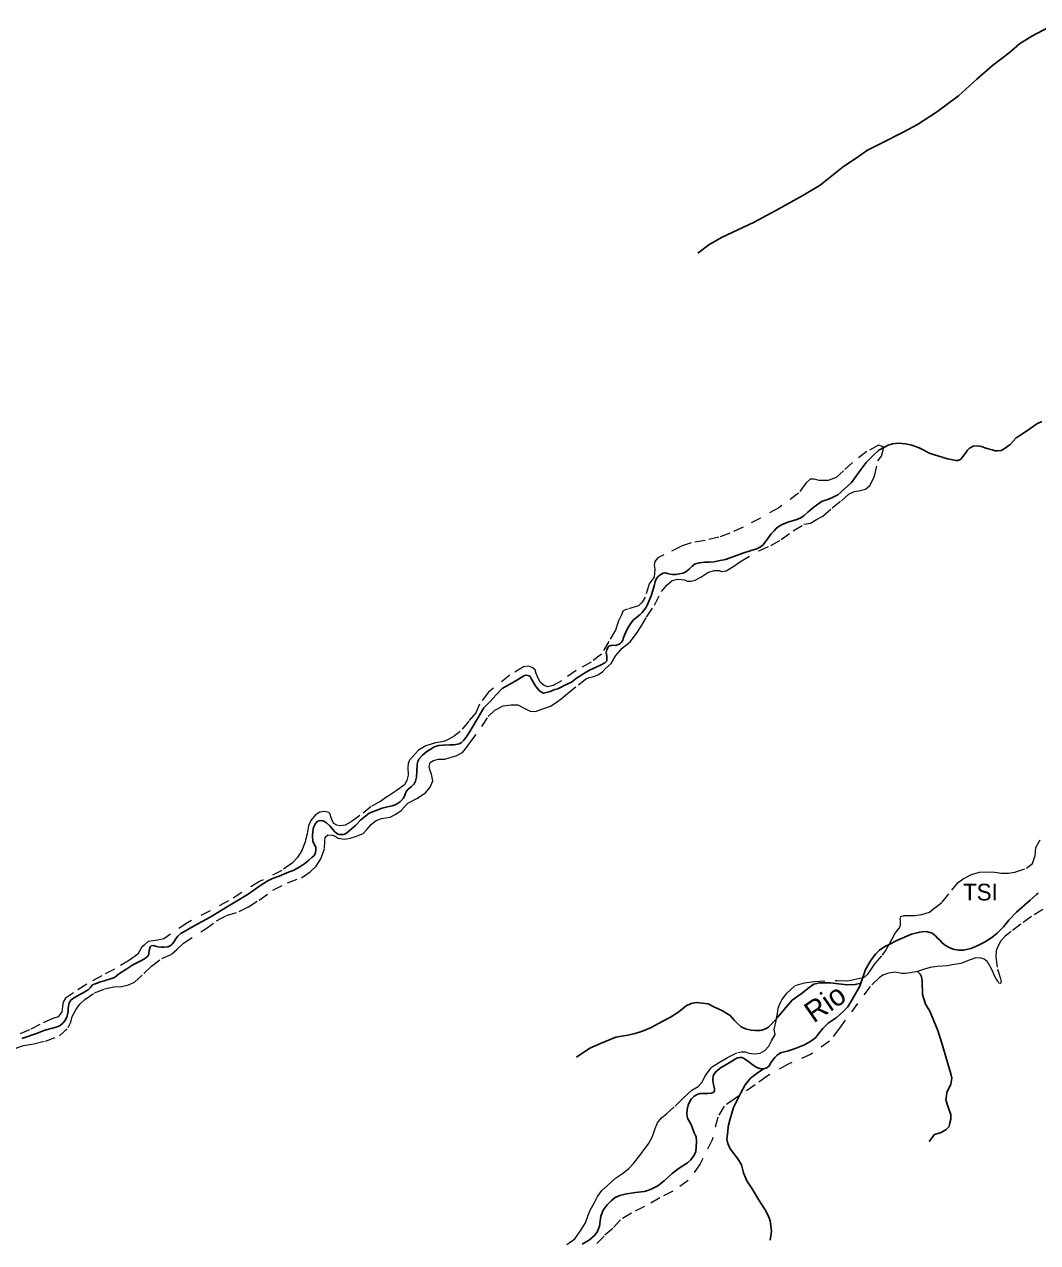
# Model space of a CAD drawing. Extents: x 391.8 to 446, y 8452 to 8507.5.
# Drawn here: x 426.58 to 436.28, y 8458.87 to 8470.53 of the extents above; entities that cross this region are included whole.
import ezdxf
from ezdxf.enums import TextEntityAlignment as Align

# ---------------------------------------------------------------- set-up
doc = ezdxf.new("R2010")
doc.units = 0
doc.header["$LTSCALE"] = 0.064
doc.linetypes.add('LONG_DASHED', pattern=[7.5, 6, -1.5])
doc.linetypes.add('SHORT_DASHED', pattern=[2.7, 1.5, -1.2])
for name, color, linetype, lineweight in [('21', 7, 'SHORT_DASHED', 13), ('7', 7, 'Continuous', 25), ('9', 7, 'LONG_DASHED', 25)]:
    doc.layers.add(name, color=color, linetype=linetype, lineweight=lineweight)
doc.layers.add('61', color=7, linetype='Continuous')

msp = doc.modelspace()

# ---------------------------------------------------------------- linework, layer by layer
at = {"layer": '21'}
for points in [[(434.7921, 8466.4881), (434.7588, 8466.5004), (434.6476, 8466.4391), (434.5089, 8466.3352), (434.4223, 8466.2544), (434.3529, 8466.1909), (434.2778, 8466.1621), (434.1911, 8466.1621), (434.1449, 8466.1736), (434.1045, 8466.1736), (434.063, 8466.138), (433.9937, 8466.0399), (433.803, 8465.9014), (433.6297, 8465.8033), (433.4621, 8465.7168), (433.335, 8465.6591), (433.231, 8465.6187), (433.0981, 8465.5898), (432.9652, 8465.5667), (432.867, 8465.5321), (432.7052, 8465.4513), (432.6474, 8465.4225), (432.6185, 8465.3878), (432.6127, 8465.3532), (432.6185, 8465.3128), (432.6127, 8465.2378), (432.565, 8465.1724), (432.5246, 8465.0454), (432.4957, 8464.9992), (432.461, 8464.9646), (432.357, 8464.93), (432.3339, 8464.9242), (432.3108, 8464.9127), (432.2992, 8464.8781), (432.269, 8464.8182), (432.2401, 8464.7316), (432.1765, 8464.622), (432.1072, 8464.5008), (432.0089, 8464.4258), (431.8645, 8464.345), (431.7258, 8464.2469), (431.6449, 8464.2008), (431.5929, 8464.1892), (431.5583, 8464.2008), (431.5236, 8464.2296), (431.5005, 8464.27), (431.4831, 8464.3162), (431.4716, 8464.3508), (431.4427, 8464.3739), (431.408, 8464.3854), (431.3618, 8464.3796), (431.2289, 8464.2989), (431.0267, 8464.1373), (430.94, 8464.0219), (430.9053, 8463.9411), (430.836, 8463.8603), (430.7551, 8463.7622), (430.6973, 8463.716), (430.6453, 8463.6872), (430.5991, 8463.6641), (430.5182, 8463.6526), (430.4258, 8463.6237), (430.3564, 8463.5833), (430.2987, 8463.5198), (430.2698, 8463.4852), (430.2582, 8463.4564), (430.2524, 8463.416), (430.256, 8463.3427), (430.2445, 8463.2908), (430.2214, 8463.2504), (430.1405, 8463.1927), (430.0538, 8463.135), (429.996, 8463.0946), (429.9036, 8463.0426), (429.7938, 8462.9561), (429.7129, 8462.8984), (429.6551, 8462.8638), (429.6031, 8462.858), (429.5742, 8462.8638), (429.5454, 8462.8811), (429.5338, 8462.9042), (429.5165, 8462.9445), (429.5107, 8462.9734), (429.4991, 8462.9849), (429.4587, 8462.9965), (429.4125, 8462.9907), (429.3662, 8462.9619), (429.3258, 8462.9099), (429.3027, 8462.858), (429.2911, 8462.783), (429.268, 8462.6964)], [(432.9284, 8465.2003), (432.966, 8465.2003), (433.0037, 8465.2079), (433.0565, 8465.238), (433.1243, 8465.2831), (433.1846, 8465.3019), (433.2336, 8465.3019), (433.2524, 8465.2907), (433.3014, 8465.2982), (433.3654, 8465.3358), (433.437, 8465.3885), (433.6141, 8465.4901), (433.7272, 8465.539), (433.8264, 8465.5968), (433.9432, 8465.6796), (434.045, 8465.7435), (434.109, 8465.7548), (434.1655, 8465.7887), (434.2258, 8465.8226), (434.3163, 8465.9016), (434.4029, 8465.9693), (434.4783, 8466.0333), (434.5273, 8466.0559), (434.5687, 8466.0634), (434.6328, 8466.0785), (434.678, 8466.1161), (434.7194, 8466.2026), (434.7534, 8466.3494), (434.7883, 8466.3957), (434.8079, 8466.4781), (434.7921, 8466.4881)], [(432.6826, 8465.1008), (432.7316, 8465.161), (432.7844, 8465.2062), (432.8333, 8465.2175), (432.8718, 8465.2154), (432.902, 8465.2116), (432.9284, 8465.2003)], [(426.9205, 8460.8489), (427.0034, 8460.928), (427.0298, 8460.9806), (427.0411, 8461.0333), (427.0767, 8461.0995), (427.1143, 8461.1522), (427.1633, 8461.1974), (427.2538, 8461.2613), (427.3517, 8461.299), (427.4384, 8461.3178), (427.5137, 8461.3215), (427.5816, 8461.3366), (427.6381, 8461.3629), (427.7285, 8461.4457), (427.8001, 8461.5172), (427.8981, 8461.5887), (427.9923, 8461.6301), (428.0413, 8461.6753), (428.1053, 8461.7355), (428.3126, 8461.871), (428.4234, 8461.9482), (428.5176, 8462.0009), (428.6382, 8462.0385), (428.7286, 8462.0837), (428.8303, 8462.1477), (428.9622, 8462.2418), (429.1016, 8462.3133), (429.2373, 8462.3622), (429.3202, 8462.4186), (429.3767, 8462.4713), (429.4219, 8462.5428), (429.4558, 8462.6407), (429.4601, 8462.7133), (429.4639, 8462.7509), (429.4865, 8462.7735), (429.5317, 8462.7697), (429.5581, 8462.7584), (429.5882, 8462.7396), (429.6448, 8462.7321), (429.7013, 8462.7396), (429.7616, 8462.7584), (429.8256, 8462.7848), (429.8633, 8462.8262), (429.9048, 8462.8751), (429.95, 8462.909), (430.0027, 8462.9278), (430.0856, 8462.9428), (430.1384, 8462.9692), (430.1911, 8463.0068), (430.2552, 8463.0745), (430.3396, 8463.1209), (430.4225, 8463.1736), (430.4677, 8463.23), (430.4941, 8463.2902), (430.479, 8463.3542), (430.4677, 8463.3843), (430.4564, 8463.4257), (430.4677, 8463.4633), (430.4979, 8463.4821), (430.5468, 8463.4972), (430.6071, 8463.4972), (430.6599, 8463.5122), (430.7239, 8463.5311), (430.7767, 8463.5612), (430.8068, 8463.595), (430.8483, 8463.6515), (430.9624, 8463.808), (431.0227, 8463.9058), (431.0868, 8463.966), (431.1659, 8464.0074), (431.2412, 8464.0149), (431.3053, 8464.0149), (431.3731, 8463.9811), (431.4259, 8463.9547), (431.4749, 8463.951), (431.5352, 8463.9736), (431.6181, 8464.0037), (431.7047, 8464.0601), (431.7838, 8464.1278), (431.8856, 8464.2069), (431.9554, 8464.2616), (431.9893, 8464.2767), (432.0345, 8464.288), (432.0722, 8464.303), (432.1174, 8464.3331), (432.1438, 8464.3595), (432.2003, 8464.4122), (432.2455, 8464.4874), (432.3058, 8464.5589), (432.3812, 8464.6191), (432.4415, 8464.6982), (432.4829, 8464.7621), (432.5394, 8464.8562), (432.6148, 8464.9691), (432.6826, 8465.1008)], [(435.1744, 8462.0111), (435.245, 8462.0334), (435.2859, 8462.0631), (435.3677, 8462.1299), (435.4614, 8462.2432), (435.5209, 8462.3174), (435.5692, 8462.3509), (435.6473, 8462.3917), (435.7253, 8462.414), (435.8034, 8462.4177), (435.8703, 8462.414), (435.9335, 8462.4065), (436.0041, 8462.4065), (436.0636, 8462.414), (436.1751, 8462.4548), (436.2309, 8462.4993), (436.2569, 8462.5736), (436.2643, 8462.6516), (436.3052, 8462.7258)], [(429.268, 8462.6964), (429.2391, 8462.6214), (429.1929, 8462.5522), (429.1467, 8462.5002), (429.0484, 8462.431), (428.8347, 8462.3271), (428.5378, 8462.1396), (428.1449, 8461.9319), (427.9831, 8461.8222), (427.9195, 8461.7761), (427.8618, 8461.7645), (427.8155, 8461.7588), (427.7693, 8461.753), (427.7289, 8461.7184), (427.7058, 8461.6953), (427.6711, 8461.6318), (427.5902, 8461.5741), (427.4457, 8461.4876), (427.3244, 8461.4241), (427.18, 8461.3433), (427.0528, 8461.2625), (426.9777, 8461.2106), (426.9546, 8461.1702), (426.9488, 8461.1298), (426.9431, 8461.0778), (426.9084, 8461.0317), (426.8564, 8461.0144), (426.7323, 8460.9595), (426.6341, 8460.9076), (426.5128, 8460.8557)], [(436.3317, 8462.059), (436.2239, 8461.9922), (436.1198, 8461.918), (436.0269, 8461.8474), (435.9711, 8461.8029), (435.9302, 8461.7583), (435.8968, 8461.6989), (435.8856, 8461.6618), (435.8819, 8461.6061), (435.8968, 8461.4873), (435.9265, 8461.3982), (435.9339, 8461.3611), (435.9228, 8461.35), (435.9116, 8461.3537), (435.9005, 8461.3723), (435.8856, 8461.3945), (435.867, 8461.4242), (435.8485, 8461.4725), (435.8262, 8461.5133), (435.8001, 8461.5579), (435.7704, 8461.5839), (435.7407, 8461.5913), (435.6886, 8461.595), (435.6366, 8461.5764), (435.5456, 8461.5428), (435.4676, 8461.5279), (435.4192, 8461.5205), (435.3189, 8461.5131), (435.252, 8461.5019), (435.1999, 8461.4871), (435.1306, 8461.4666)], [(434.8596, 8461.7238), (434.8881, 8461.7773), (434.9142, 8461.8255), (434.9402, 8461.8589), (434.9588, 8461.8812), (434.9699, 8461.9072), (434.9699, 8461.948), (434.9662, 8461.9666), (434.9736, 8461.9926), (435.0034, 8462), (435.1075, 8462), (435.1744, 8462.0111)], [(434.6082, 8461.4088), (434.6279, 8461.4135), (434.6577, 8461.4394), (434.6837, 8461.4803), (434.7246, 8461.5397), (434.7952, 8461.6213), (434.825, 8461.6622), (434.8584, 8461.7216), (434.8596, 8461.7238)], [(435.1306, 8461.4666), (435.0661, 8461.4537), (435.0141, 8461.4463), (434.9769, 8461.4463), (434.9509, 8461.4537), (434.9137, 8461.4574), (434.8542, 8461.45), (434.7985, 8461.4314), (434.765, 8461.4054), (434.6772, 8461.3209), (434.3844, 8460.924)], [(433.7831, 8461.0161), (433.7903, 8461.0625), (433.7977, 8461.1145), (433.8126, 8461.1553), (433.8349, 8461.1962), (433.8795, 8461.2593), (433.9612, 8461.3298), (434.0505, 8461.3558), (434.1434, 8461.3707), (434.364, 8461.38), (434.4644, 8461.3763), (434.5499, 8461.3949), (434.6082, 8461.4088)], [(431.7765, 8458.8528), (431.8508, 8458.9084), (431.9066, 8458.9827), (431.9549, 8459.0606), (431.9809, 8459.1349), (431.9995, 8459.1832), (432.0404, 8459.2537), (432.0701, 8459.3131), (432.111, 8459.3688), (432.1631, 8459.417), (432.2411, 8459.4876), (432.308, 8459.5321), (432.3675, 8459.5804), (432.4121, 8459.6286), (432.4725, 8459.7056), (432.5059, 8459.7501), (432.558, 8459.8169), (432.5952, 8459.8875), (432.6212, 8459.9617), (432.6435, 8460.0174), (432.6807, 8460.0657), (432.729, 8460.1028), (432.8108, 8460.177), (432.8814, 8460.2476), (432.9334, 8460.2958), (432.9706, 8460.3292), (433.0338, 8460.3664), (433.071, 8460.4072), (433.1007, 8460.4666), (433.1602, 8460.5483), (433.2271, 8460.5928), (433.3126, 8460.6411), (433.4111, 8460.6913), (433.4483, 8460.695), (433.4817, 8460.695), (433.5189, 8460.6839), (433.5672, 8460.6764), (433.6267, 8460.6839), (433.6713, 8460.7099), (433.7085, 8460.7507), (433.7345, 8460.8027), (433.7679, 8460.8621), (433.7605, 8460.9103), (433.7828, 8461.0143), (433.7831, 8461.0161)], [(434.3844, 8460.924), (434.2903, 8460.7987), (434.1125, 8460.6734), (433.8929, 8460.5794), (433.6942, 8460.4645), (433.5791, 8460.3809), (433.4271, 8460.2777)], [(426.3591, 8460.6344), (426.4232, 8460.6833), (426.5023, 8460.7323), (426.5739, 8460.7586), (426.6756, 8460.7737), (426.7849, 8460.8), (426.9205, 8460.8489)], [(433.4271, 8460.2777), (433.3867, 8460.2503), (433.2821, 8460.1772), (433.2194, 8460.0727), (433.1671, 8459.8534), (433.0521, 8459.6236), (432.937, 8459.4669), (432.7906, 8459.3625), (432.6651, 8459.2998), (432.5187, 8459.2163), (432.3932, 8459.1536), (432.2886, 8459.0909), (432.2154, 8459.0074), (432.1317, 8458.9343), (432.0272, 8458.8298)]]:
    msp.add_lwpolyline(points, dxfattribs=at)
at = {"layer": '7'}
msp.add_line((434.5893, 8461.3534), (434.6082, 8461.4088), dxfattribs=at)
for points in [[(434.8079, 8466.4781), (434.8098, 8466.4792), (434.8511, 8466.4998), (434.8925, 8466.513), (434.9488, 8466.5186), (435.0164, 8466.513), (435.0765, 8466.4998), (435.1479, 8466.4755), (435.2531, 8466.4211), (435.4203, 8466.3704), (435.4686, 8466.3589), (435.5005, 8466.3532), (435.5174, 8466.3532), (435.5418, 8466.3626), (435.5606, 8466.3814), (435.5757, 8466.4039), (435.5926, 8466.4283), (435.6113, 8466.4527), (435.6301, 8466.4714), (435.6658, 8466.4902), (435.7053, 8466.4939), (435.7447, 8466.4864), (435.7748, 8466.4733), (435.8067, 8466.4639), (435.8461, 8466.4545), (435.8762, 8466.447), (435.8931, 8466.447), (435.9326, 8466.4508), (435.9626, 8466.4658), (436.0171, 8466.5071), (436.0753, 8466.569), (436.138, 8466.6091), (436.2056, 8466.656), (436.2751, 8466.7048), (436.3221, 8466.7254)], [(433.6282, 8465.5274), (433.6545, 8465.5462), (433.6714, 8465.5687), (433.6996, 8465.6081), (433.7315, 8465.6531), (433.7597, 8465.6812), (433.781, 8465.7063), (433.8073, 8465.7251), (433.8355, 8465.7401), (433.8918, 8465.7626), (433.9763, 8465.7889), (434.0139, 8465.8039), (434.0458, 8465.8264), (434.0815, 8465.8602), (434.1416, 8465.9089), (434.2205, 8465.9633), (434.2628, 8465.9773), (434.3191, 8465.9998), (434.368, 8466.0242), (434.4281, 8466.0749), (434.4994, 8466.1424), (434.584, 8466.2568), (434.6389, 8466.3348), (434.7065, 8466.4004), (434.761, 8466.4511), (434.8079, 8466.4781)], [(433.2281, 8465.3923), (433.2939, 8465.4055), (433.3746, 8465.4336), (433.461, 8465.4655), (433.5381, 8465.4936), (433.5925, 8465.5087), (433.6282, 8465.5274)], [(430.339, 8463.3774), (430.3428, 8463.4472), (430.3484, 8463.4754), (430.3634, 8463.4998), (430.3935, 8463.5335), (430.4348, 8463.5692), (430.4724, 8463.5917), (430.5062, 8463.6142), (430.5513, 8463.6255), (430.5907, 8463.6292), (430.6527, 8463.6348), (430.6959, 8463.6348), (430.7437, 8463.6421), (430.7644, 8463.6533), (430.7907, 8463.6796), (430.8207, 8463.719), (430.8677, 8463.7921), (430.9259, 8463.8934), (430.9804, 8463.9872), (431.0405, 8464.0491), (431.1006, 8464.1129), (431.157, 8464.1711), (431.2877, 8464.245), (431.3384, 8464.2787), (431.3628, 8464.2937), (431.3797, 8464.2994), (431.4023, 8464.2975), (431.4154, 8464.2937), (431.423, 8464.2881), (431.4361, 8464.2619), (431.4774, 8464.1924), (431.5131, 8464.1493), (431.5319, 8464.138), (431.5526, 8464.1287), (431.5657, 8464.1324), (431.6052, 8464.1399), (431.6371, 8464.153), (431.6596, 8464.1624), (431.6878, 8464.1681), (431.7216, 8464.1849), (431.7498, 8464.1999), (431.8193, 8464.2337), (431.8681, 8464.2712), (431.9282, 8464.3106), (431.9921, 8464.3463), (432.0616, 8464.3782), (432.1029, 8464.3988), (432.1405, 8464.4176), (432.148, 8464.4269), (432.1574, 8464.4382), (432.1593, 8464.4588), (432.1574, 8464.4832), (432.1518, 8464.517), (432.1574, 8464.5432), (432.1668, 8464.5658), (432.1781, 8464.577), (432.2081, 8464.5864), (432.2443, 8464.5837), (432.2613, 8464.5893), (432.2838, 8464.5987), (432.2951, 8464.6118), (432.3101, 8464.6325), (432.3176, 8464.6587), (432.3383, 8464.7056), (432.357, 8464.7469), (432.3833, 8464.79), (432.4096, 8464.8276), (432.4453, 8464.8538), (432.4735, 8464.8782), (432.4961, 8464.8989), (432.5317, 8464.9439), (432.5468, 8464.9758), (432.5811, 8465.0597), (432.6111, 8465.1516), (432.6224, 8465.1948), (432.6336, 8465.2248), (432.6449, 8465.2398), (432.6693, 8465.2585), (432.6975, 8465.2754), (432.7163, 8465.2792), (432.7388, 8465.2736), (432.752, 8465.2679), (432.7858, 8465.2642), (432.8177, 8465.2642), (432.8572, 8465.2698), (432.8891, 8465.2754), (432.9154, 8465.2886), (432.9473, 8465.3129), (432.9755, 8465.343), (433.0037, 8465.3636), (433.045, 8465.3749), (433.092, 8465.3805), (433.1408, 8465.3805), (433.1859, 8465.3842), (433.2281, 8465.3923)], [(430.2394, 8463.1898), (430.2563, 8463.2085), (430.2864, 8463.2311), (430.3127, 8463.2611), (430.3258, 8463.2873), (430.3352, 8463.3249), (430.339, 8463.3774)], [(427.0115, 8461.1639), (427.0284, 8461.1901), (427.0453, 8461.2033), (427.1081, 8461.2416), (427.1457, 8461.2603), (427.172, 8461.2754), (427.1927, 8461.2904), (427.2133, 8461.3072), (427.2283, 8461.3279), (427.2396, 8461.3391), (427.2659, 8461.3485), (427.3016, 8461.3616), (427.3467, 8461.3748), (427.4068, 8461.3935), (427.4462, 8461.4085), (427.4838, 8461.4386), (427.5646, 8461.4892), (427.6209, 8461.5286), (427.6904, 8461.5642), (427.7336, 8461.5849), (427.7505, 8461.598), (427.7656, 8461.613), (427.775, 8461.6299), (427.7794, 8461.6665), (427.7869, 8461.7003), (427.7981, 8461.7097), (427.8169, 8461.7134), (427.8395, 8461.7078), (427.8639, 8461.7003), (427.8921, 8461.6984), (427.9221, 8461.6965), (427.9578, 8461.7003), (427.9785, 8461.7097), (427.9954, 8461.7247), (428.0142, 8461.7472), (428.0311, 8461.7753), (428.0536, 8461.8016), (428.0799, 8461.8279), (428.2095, 8461.901), (428.3617, 8461.9854), (428.5505, 8462.0991), (428.7252, 8462.206), (428.8379, 8462.2848), (428.9082, 8462.3289), (428.9571, 8462.3551), (429.0228, 8462.3777), (429.0961, 8462.4077), (429.1618, 8462.4339), (429.22, 8462.4658), (429.267, 8462.4977), (429.3064, 8462.5315), (429.3384, 8462.5577), (429.359, 8462.5784), (429.3703, 8462.6046), (429.3741, 8462.6253), (429.3741, 8462.6515), (429.3665, 8462.6684), (429.3459, 8462.7078), (429.3402, 8462.7585), (429.344, 8462.8091), (429.3517, 8462.8435), (429.3668, 8462.8754), (429.3818, 8462.8961), (429.3931, 8462.9036), (429.4043, 8462.9073), (429.4193, 8462.9092), (429.4381, 8462.9073), (429.4494, 8462.9036), (429.4738, 8462.8886), (429.5058, 8462.8585), (429.5358, 8462.8229), (429.5565, 8462.8023), (429.5715, 8462.7891), (429.5846, 8462.7798), (429.5959, 8462.776), (429.6147, 8462.7741), (429.6372, 8462.7741), (429.6579, 8462.7816), (429.688, 8462.8079), (429.7556, 8462.866), (429.8025, 8462.9167), (429.8514, 8462.9542), (429.8833, 8462.9786), (429.9246, 8462.9955), (429.966, 8463.0124), (430.0073, 8463.0274), (430.0467, 8463.0386), (430.1023, 8463.051), (430.1323, 8463.0585), (430.1549, 8463.0716), (430.1849, 8463.0922), (430.2075, 8463.1185), (430.2225, 8463.141), (430.23, 8463.171), (430.2394, 8463.1898)], [(434.8596, 8461.7238), (434.9417, 8461.7657), (435.0757, 8461.8226), (435.1526, 8461.8418), (435.2, 8461.8469), (435.2282, 8461.8431), (435.25, 8461.838), (435.2705, 8461.8303), (435.3025, 8461.8072), (435.3217, 8461.7855), (435.3474, 8461.7624), (435.3691, 8461.7381), (435.3986, 8461.7138), (435.4345, 8461.6946), (435.4742, 8461.678), (435.5242, 8461.6703), (435.5729, 8461.669), (435.6405, 8461.684), (435.7033, 8461.7096), (435.7725, 8461.7455), (435.8443, 8461.7915), (435.8955, 8461.8325), (435.9545, 8461.8927), (436.0059, 8461.9562), (436.0802, 8462.0317), (436.2096, 8462.1469), (436.2712, 8462.2007), (436.2853, 8462.2147)], [(434.6082, 8461.4088), (434.6334, 8461.4828), (434.6879, 8461.5762), (434.7289, 8461.6313), (434.7687, 8461.6697), (434.8186, 8461.7029), (434.8596, 8461.7238)], [(433.6571, 8460.535), (433.6666, 8460.5369), (433.6884, 8460.5433), (433.7127, 8460.5612), (433.732, 8460.597), (433.7666, 8460.6431), (433.7896, 8460.6661), (433.8217, 8460.6866), (433.8973, 8460.7071), (433.9703, 8460.7327), (434.0502, 8460.764), (434.1117, 8460.7985), (434.154, 8460.8318), (434.1835, 8460.8677), (434.2271, 8460.9201), (434.2771, 8460.97), (434.3539, 8461.0219), (434.4167, 8461.0783), (434.4638, 8461.1285), (434.5046, 8461.1912), (434.58, 8461.3261), (434.5893, 8461.3534)], [(434.5893, 8461.3534), (434.5337, 8461.3401), (434.4563, 8461.3375), (434.3256, 8461.3527), (434.2963, 8461.3553), (434.251, 8461.358), (434.1977, 8461.3553), (434.139, 8461.3447), (434.0956, 8461.3119), (434.0182, 8461.2506), (433.9329, 8461.1894), (433.7831, 8461.0161)], [(426.9514, 8460.9706), (426.9702, 8460.9932), (426.989, 8461.0269), (427.0021, 8461.0832), (427.0021, 8461.1076), (427.0059, 8461.1339), (427.0115, 8461.1639)], [(426.56, 8460.8255), (426.699, 8460.8724), (426.7798, 8460.9024), (426.8537, 8460.9219), (426.897, 8460.935), (426.927, 8460.95), (426.9514, 8460.9706)], [(433.7831, 8461.0161), (433.7809, 8461.0136), (433.7062, 8460.9337), (433.6769, 8460.9151), (433.6422, 8460.9044), (433.6236, 8460.8991), (433.5809, 8460.8991), (433.5383, 8460.9044), (433.4849, 8460.9178), (433.4449, 8460.9364), (433.4058, 8460.9721)], [(432.929, 8459.636), (432.9623, 8459.6629), (432.9789, 8459.6859), (432.9956, 8459.7089), (433.011, 8459.7435), (433.0135, 8459.7857), (433.0161, 8459.8382), (433.0123, 8459.883), (432.9956, 8459.9214), (432.9659, 8460.0002), (432.9313, 8460.0629), (432.9236, 8460.1013), (432.9274, 8460.1435), (432.9377, 8460.1865), (432.9492, 8460.216), (432.9659, 8460.2441), (432.9928, 8460.2736), (433.0222, 8460.2889), (433.0517, 8460.2966), (433.085, 8460.2979), (433.1261, 8460.2992), (433.1607, 8460.3017), (433.1812, 8460.3107), (433.1888, 8460.3222), (433.1901, 8460.3439), (433.1824, 8460.3721), (433.1748, 8460.3964), (433.1722, 8460.4348), (433.1773, 8460.4655), (433.1879, 8460.4906), (433.2084, 8460.5111), (433.252, 8460.5469), (433.3276, 8460.5917), (433.3865, 8460.6276), (433.4096, 8460.6391), (433.4314, 8460.6417), (433.4519, 8460.6417), (433.4673, 8460.6353), (433.4762, 8460.6289), (433.5172, 8460.5994), (433.5595, 8460.5687), (433.5954, 8460.5457), (433.6218, 8460.5356), (433.6474, 8460.533), (433.6571, 8460.535)], [(432.6015, 8459.3908), (432.6477, 8459.4152), (432.7079, 8459.4612), (432.7848, 8459.5329), (432.8405, 8459.5784), (432.8867, 8459.6065), (432.929, 8459.636)], [(431.9206, 8458.8569), (431.9919, 8458.899), (432.0438, 8458.9411), (432.0697, 8458.9768), (432.0892, 8459.0286), (432.1021, 8459.1257), (432.1216, 8459.1808), (432.1599, 8459.2318), (432.2009, 8459.2715), (432.2381, 8459.3022), (432.2816, 8459.3226), (432.347, 8459.3393), (432.4329, 8459.3521), (432.517, 8459.3601), (432.5592, 8459.3729), (432.6015, 8459.3908)]]:
    msp.add_lwpolyline(points, dxfattribs=at)
at = {"layer": '9'}
for points in [[(433.0295, 8468.3378), (433.1339, 8468.4159), (433.2556, 8468.4854), (433.5686, 8468.633), (433.7772, 8468.7458), (434.0337, 8468.8891), (434.1989, 8468.989), (434.4249, 8469.167), (434.5447, 8469.2473), (434.6534, 8469.3211), (434.7881, 8469.3906), (435.0011, 8469.4991), (435.1315, 8469.5686), (435.3141, 8469.6858), (435.5228, 8469.8421), (435.701, 8470.0027), (435.8488, 8470.133), (436.0075, 8470.2524), (436.1074, 8470.3392), (436.2248, 8470.413), (436.4378, 8470.5259)], [(435.243, 8459.8402), (435.2928, 8459.9041), (435.3567, 8459.9254), (435.4065, 8459.9537), (435.4349, 8459.9821), (435.442, 8460.0176), (435.4491, 8460.0531), (435.4491, 8460.0957), (435.428, 8460.1573), (435.412, 8460.2054), (435.4039, 8460.2415), (435.408, 8460.2736), (435.412, 8460.3097), (435.432, 8460.3458), (435.4521, 8460.3859), (435.4602, 8460.446), (435.4521, 8460.4861), (435.42, 8460.5944), (435.3638, 8460.7788), (435.3277, 8460.8991), (435.2511, 8461.0857), (435.2069, 8461.1535), (435.1788, 8461.2457), (435.1775, 8461.3765), (435.1695, 8461.4126), (435.1587, 8461.4386), (435.1306, 8461.4666)], [(431.8666, 8460.646), (431.9958, 8460.7321), (432.0964, 8460.7751), (432.2448, 8460.8373), (432.3597, 8460.8564), (432.4307, 8460.8729), (432.5, 8460.8942), (432.5774, 8460.9262), (432.6227, 8460.9528), (432.6867, 8460.9874), (432.7667, 8461.0273), (432.8467, 8461.0806), (432.916, 8461.1365), (432.964, 8461.1578), (433.0147, 8461.1685), (433.0707, 8461.1632), (433.1267, 8461.1552), (433.1773, 8461.1312), (433.2653, 8461.0886), (433.3373, 8461.0433), (433.3773, 8460.9981), (433.4058, 8460.9721)], [(433.6571, 8460.535), (433.5984, 8460.4936), (433.5348, 8460.446), (433.4831, 8460.3824), (433.4393, 8460.303), (433.4271, 8460.2777)], [(433.4271, 8460.2777), (433.3717, 8460.1629), (433.3399, 8460.0557), (433.3189, 8459.9823), (433.3149, 8459.9346), (433.3069, 8459.8598), (433.3177, 8459.8203), (433.3394, 8459.7684), (433.4115, 8459.6744), (433.4473, 8459.6148), (433.4672, 8459.5393), (433.499, 8459.4639), (433.5507, 8459.3844), (433.6103, 8459.2851), (433.674, 8459.1858), (433.7066, 8459.1235), (433.7225, 8459.0798), (433.7353, 8458.9821), (433.7205, 8458.8934)]]:
    msp.add_lwpolyline(points, dxfattribs=at)

# ---------------------------------------------------------------- texts
at = {"layer": '61'}
msp.add_text('Rio                                                           Arrojadinho', height=0.2, rotation=34.698, dxfattribs=at).set_placement((436.6675, 8462.7175), align=Align.CENTER)
msp.add_text('TSI', height=0.16, dxfattribs=at).set_placement((435.7338, 8462.1445), align=Align.CENTER)

doc.saveas('drawing.dxf')
